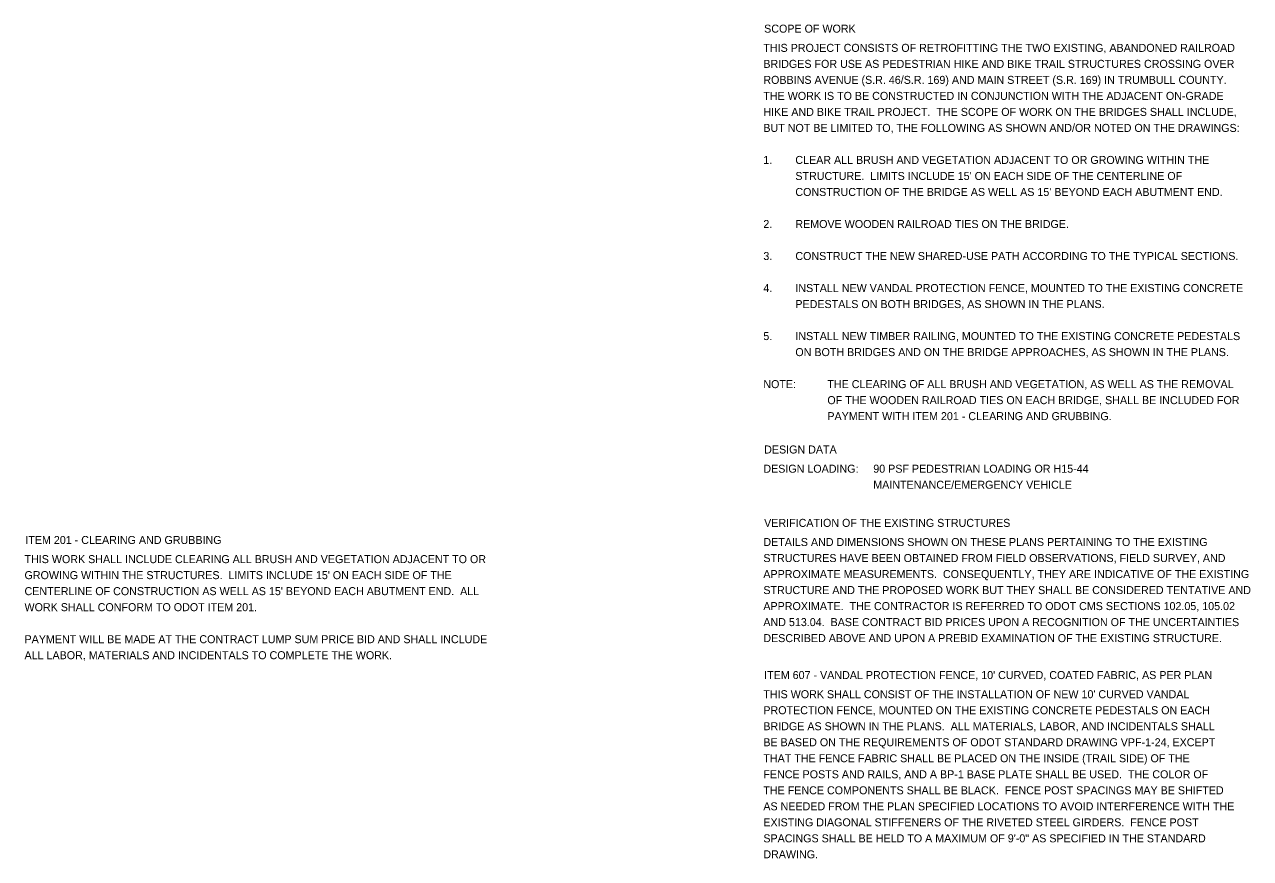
# Model space of a CAD drawing. Extents: x -10.6 to 33.4, y -28.4 to 21.5.
# Drawn here: x -10.55 to 10.89, y 6.71 to 21.3 of the extents above; entities that cross this region are included whole.
import ezdxf

# ---------------------------------------------------------------- set-up
doc = ezdxf.new("R2010")
doc.units = 0
doc.layers.add('BR_P_Gen_Text', color=7, linetype='Continuous')

msp = doc.modelspace()

# ---------------------------------------------------------------- texts
at = {"layer": 'BR_P_Gen_Text'}
for s, p in [('SCOPE OF WORK', (2.382, 21.155)), ('THIS PROJECT CONSISTS OF RETROFITTING THE TWO EXISTING, ABANDONED RAILROAD', (2.368, 20.819)), ('BRIDGES FOR USE AS PEDESTRIAN HIKE AND BIKE TRAIL STRUCTURES CROSSING OVER', (2.368, 20.539)), ('ROBBINS AVENUE (S.R. 46/S.R. 169) AND MAIN STREET (S.R. 169) IN TRUMBULL COUNTY.', (2.368, 20.259)), ('THE WORK IS TO BE CONSTRUCTED IN CONJUNCTION WITH THE ADJACENT ON-GRADE', (2.368, 19.979)), ('HIKE AND BIKE TRAIL PROJECT.  THE SCOPE OF WORK ON THE BRIDGES SHALL INCLUDE,', (2.368, 19.699)), ('BUT NOT BE LIMITED TO, THE FOLLOWING AS SHOWN AND/OR NOTED ON THE DRAWINGS:', (2.368, 19.419)), ('1.', (2.368, 18.859)), ('CLEAR ALL BRUSH AND VEGETATION ADJACENT TO OR GROWING WITHIN THE', (2.928, 18.859)), ("STRUCTURE.  LIMITS INCLUDE 15' ON EACH SIDE OF THE CENTERLINE OF", (2.928, 18.579)), ("CONSTRUCTION OF THE BRIDGE AS WELL AS 15' BEYOND EACH ABUTMENT END.", (2.928, 18.299)), ('2.', (2.368, 17.739)), ('REMOVE WOODEN RAILROAD TIES ON THE BRIDGE.', (2.928, 17.739)), ('3.', (2.368, 17.179)), ('CONSTRUCT THE NEW SHARED-USE PATH ACCORDING TO THE TYPICAL SECTIONS.', (2.928, 17.179)), ('4.', (2.368, 16.619)), ('INSTALL NEW VANDAL PROTECTION FENCE, MOUNTED TO THE EXISTING CONCRETE', (2.928, 16.619)), ('PEDESTALS ON BOTH BRIDGES, AS SHOWN IN THE PLANS.', (2.928, 16.339)), ('5.', (2.368, 15.779)), ('INSTALL NEW TIMBER RAILING, MOUNTED TO THE EXISTING CONCRETE PEDESTALS', (2.928, 15.779)), ('ON BOTH BRIDGES AND ON THE BRIDGE APPROACHES, AS SHOWN IN THE PLANS.', (2.928, 15.499)), ('NOTE:', (2.368, 14.939)), ('THE CLEARING OF ALL BRUSH AND VEGETATION, AS WELL AS THE REMOVAL', (3.488, 14.939)), ('OF THE WOODEN RAILROAD TIES ON EACH BRIDGE, SHALL BE INCLUDED FOR', (3.488, 14.659)), ('PAYMENT WITH ITEM 201 - CLEARING AND GRUBBING.', (3.488, 14.379)), ('DESIGN DATA', (2.382, 13.796)), ('DESIGN LOADING:', (2.368, 13.46)), ('90 PSF PEDESTRIAN LOADING OR H15-44', (4.291, 13.46)), ('MAINTENANCE/EMERGENCY VEHICLE', (4.291, 13.18)), ('VERIFICATION OF THE EXISTING STRUCTURES', (2.382, 12.513)), ('ITEM 201 - CLEARING AND GRUBBING', (-10.541, 12.214)), ('DETAILS AND DIMENSIONS SHOWN ON THESE PLANS PERTAINING TO THE EXISTING', (2.368, 12.178)), ('THIS WORK SHALL INCLUDE CLEARING ALL BRUSH AND VEGETATION ADJACENT TO OR', (-10.555, 11.879)), ('STRUCTURES HAVE BEEN OBTAINED FROM FIELD OBSERVATIONS, FIELD SURVEY, AND', (2.368, 11.898)), ("GROWING WITHIN THE STRUCTURES.  LIMITS INCLUDE 15' ON EACH SIDE OF THE", (-10.555, 11.599)), ('APPROXIMATE MEASUREMENTS.  CONSEQUENTLY, THEY ARE INDICATIVE OF THE EXISTING', (2.368, 11.618)), ("CENTERLINE OF CONSTRUCTION AS WELL AS 15' BEYOND EACH ABUTMENT END.  ALL", (-10.555, 11.319)), ('STRUCTURE AND THE PROPOSED WORK BUT THEY SHALL BE CONSIDERED TENTATIVE AND', (2.368, 11.338)), ('WORK SHALL CONFORM TO ODOT ITEM 201.', (-10.555, 11.039)), ('APPROXIMATE.  THE CONTRACTOR IS REFERRED TO ODOT CMS SECTIONS 102.05, 105.02', (2.368, 11.058)), ('AND 513.04.  BASE CONTRACT BID PRICES UPON A RECOGNITION OF THE UNCERTAINTIES', (2.368, 10.778)), ('PAYMENT WILL BE MADE AT THE CONTRACT LUMP SUM PRICE BID AND SHALL INCLUDE', (-10.555, 10.479)), ('DESCRIBED ABOVE AND UPON A PREBID EXAMINATION OF THE EXISTING STRUCTURE.', (2.368, 10.498)), ('ALL LABOR, MATERIALS AND INCIDENTALS TO COMPLETE THE WORK.', (-10.555, 10.199)), ("ITEM 607 - VANDAL PROTECTION FENCE, 10' CURVED, COATED FABRIC, AS PER PLAN", (2.382, 9.852)), ("THIS WORK SHALL CONSIST OF THE INSTALLATION OF NEW 10' CURVED VANDAL", (2.368, 9.517)), ('PROTECTION FENCE, MOUNTED ON THE EXISTING CONCRETE PEDESTALS ON EACH', (2.368, 9.237)), ('BRIDGE AS SHOWN IN THE PLANS.  ALL MATERIALS, LABOR, AND INCIDENTALS SHALL', (2.368, 8.957)), ('BE BASED ON THE REQUIREMENTS OF ODOT STANDARD DRAWING VPF-1-24, EXCEPT', (2.368, 8.677)), ('THAT THE FENCE FABRIC SHALL BE PLACED ON THE INSIDE (TRAIL SIDE) OF THE', (2.368, 8.397)), ('FENCE POSTS AND RAILS, AND A BP-1 BASE PLATE SHALL BE USED.  THE COLOR OF', (2.368, 8.117)), ('THE FENCE COMPONENTS SHALL BE BLACK.  FENCE POST SPACINGS MAY BE SHIFTED', (2.368, 7.837)), ('AS NEEDED FROM THE PLAN SPECIFIED LOCATIONS TO AVOID INTERFERENCE WITH THE', (2.368, 7.557)), ('EXISTING DIAGONAL STIFFENERS OF THE RIVETED STEEL GIRDERS.  FENCE POST', (2.368, 7.277)), ('SPACINGS SHALL BE HELD TO A MAXIMUM OF 9\'-0" AS SPECIFIED IN THE STANDARD', (2.368, 6.997)), ('DRAWING.', (2.368, 6.717))]:
    msp.add_text(s, height=0.14, dxfattribs=at).set_placement(p)

doc.saveas('drawing.dxf')
